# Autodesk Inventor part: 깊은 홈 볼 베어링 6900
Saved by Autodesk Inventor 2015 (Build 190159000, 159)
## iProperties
Created: 2026-05
Part Number: 깊은 홈 볼 베어링 6900
Material: 일반
Document SubType Name: Modeling
Designer: 104
Density: 1 g/cm^3
Appearance: 기본값
Author: 104
Author: jhkim
Description: 깊은 그루브 볼 베어링
Creation Date: 2026-04-27
Sending System: Autodesk Inventor 2027
Preprocessor: ST-DEVELOPER v20.1
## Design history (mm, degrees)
node "깊은 홈 볼 베어링 69001"
body "Solid1"
node "Solid1_1"
node "Solid1_2"
node "Solid1_3"
node "Solid1_4"
node "Solid1_5"
node "Solid1_6"
node "Solid1_7"
node "Solid1_8"
node "Solid1_9"
node "기준1"
node "기준2"
node "기준3"
node "기준4"
node "기준5"
node "기준6"
node "기준7"
node "기준8"
node "기준9"
node "기준10"
